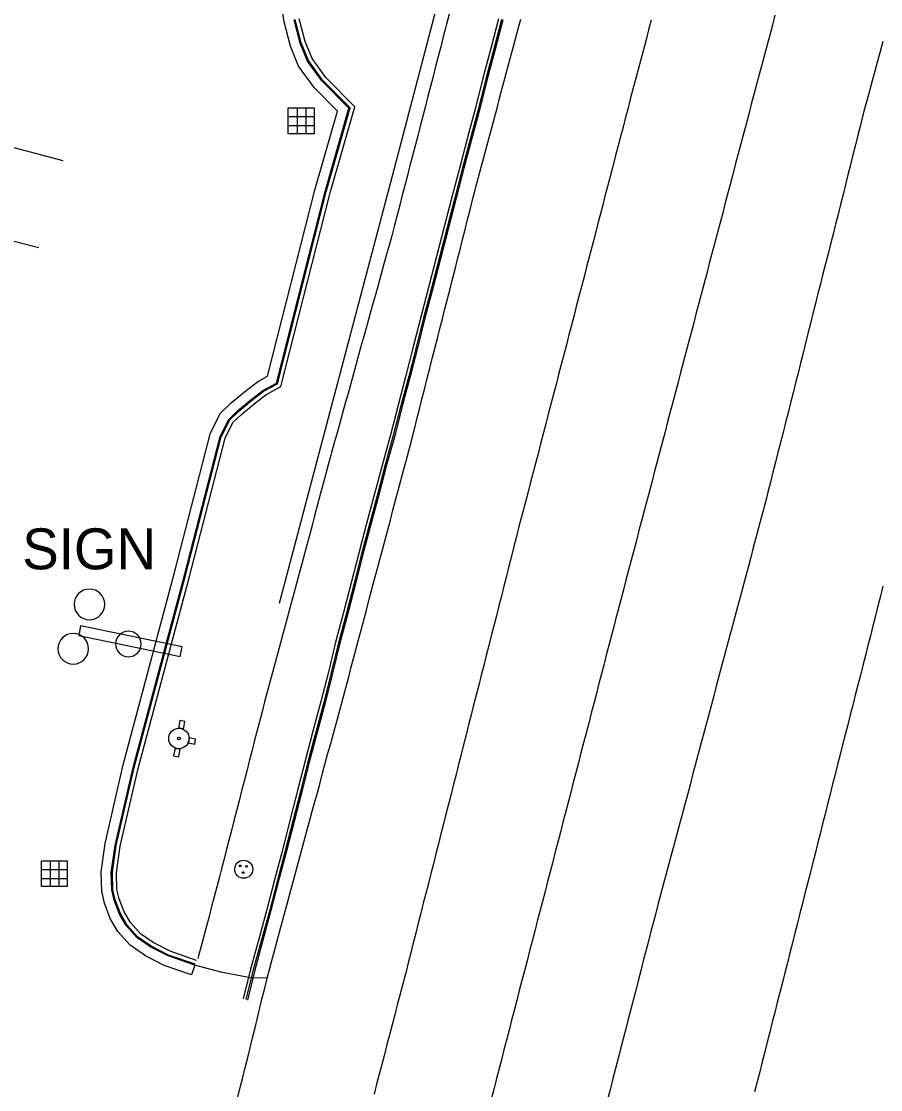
# Model space of a CAD drawing. Extents: x 1901471 to 1963503, y 756461 to 799997.
# Drawn here: x 1929483.1 to 1929567.1, y 772408.7 to 772513.2 of the extents above; entities that cross this region are included whole.
import ezdxf

# ---------------------------------------------------------------- set-up
doc = ezdxf.new("R2010")
doc.units = 0
for name, color, linetype in [('Default', 7, 'Continuous'), ('RD_EX_Bldg', 7, 'Continuous'), ('RD_EX_Conc', 7, 'Continuous'), ('RD_EX_DR_Inlet', 7, 'Continuous'), ('RD_EX_Fence_Other', 7, 'Continuous'), ('RD_EX_Misc', 7, 'Continuous'), ('RD_EX_Road', 7, 'Continuous'), ('RD_EX_UT', 7, 'Continuous'), ('RD_HC_Cl', 7, 'Continuous')]:
    doc.layers.add(name, color=color, linetype=linetype)

# ---------------------------------------------------------------- blocks, each defined once
blk = doc.blocks.new('POST')
at = {"layer": 'Default'}
for start, end in [(90, 270), (270, 90)]:
    blk.add_arc((0, 0), 0.127, start, end, dxfattribs=at)
blk = doc.blocks.new('MH')
at = {"layer": 'RD_EX_DR_Inlet'}
for centre, radius in [((0, 0), 1.75), ((-0.66, 0.63), 0.175), ((0.56, 0.56), 0.175), ((-0.09, -0.66), 0.175)]:
    blk.add_circle(centre, radius, dxfattribs=at)
blk = doc.blocks.new('SIGNPOST')
at = {"layer": 'Default'}
for start, end in [(90, 270), (270, 90)]:
    blk.add_arc((0, 0), 0.127, start, end, dxfattribs=at)
blk = doc.blocks.new('DI')
at = {"layer": 'RD_EX_DR_Inlet'}
for p, q in [((-0.84, 2.56), (-0.84, -2.44)), ((0.86, 2.56), (0.86, -2.44)), ((-2.54, 0.86), (2.46, 0.86)), ((-2.54, -0.84), (2.46, -0.84))]:
    blk.add_line(p, q, dxfattribs=at)
blk.add_lwpolyline([(-2.54, -2.44), (-2.54, 2.56), (2.46, 2.56), (2.46, -2.44)], close=True, dxfattribs=at)

msp = doc.modelspace()

# ---------------------------------------------------------------- linework, layer by layer
at = {"layer": 'RD_EX_Bldg'}
msp.add_lwpolyline([(1929488.71, 772453.14), (1929498.62, 772451.09), (1929498.81, 772452.03), (1929488.9, 772454.09)], close=True, dxfattribs=at)
at = {"layer": 'RD_EX_Conc'}
for points in [[(1929500.07, 772420.91), (1929497.46, 772421.81), (1929495.75, 772422.68), (1929494.4, 772423.6), (1929493.36, 772424.78), (1929492.71, 772425.91), (1929492.18, 772427.26), (1929491.95, 772428.26), (1929491.9, 772429.97), (1929492.28, 772432.62), (1929494.03, 772440.25), (1929499.05, 772459.04), (1929502.55, 772472.6), (1929503.38, 772474.27), (1929504.28, 772475.14), (1929505.54, 772476.19), (1929506.72, 772477.1), (1929508.05, 772477.81), (1929512.8, 772496.54), (1929515.13, 772504.7), (1929512.49, 772507.36), (1929511.09, 772509.3), (1929510.37, 772511.05), (1929509.78, 772513.34)], [(1929500.11, 772421), (1929497.5, 772421.9), (1929495.8, 772422.76), (1929494.47, 772423.68), (1929493.45, 772424.83), (1929492.8, 772425.95), (1929492.27, 772427.29), (1929492.05, 772428.27), (1929492, 772429.97), (1929492.37, 772432.6), (1929494.12, 772440.23), (1929499.15, 772459.02), (1929502.64, 772472.56), (1929503.47, 772474.21), (1929504.35, 772475.06), (1929505.6, 772476.11), (1929506.78, 772477.01), (1929508.13, 772477.74), (1929512.9, 772496.51), (1929515.25, 772504.73), (1929512.56, 772507.42), (1929511.17, 772509.35), (1929510.47, 772511.09), (1929509.88, 772513.36)], [(1929500.24, 772421.38), (1929497.65, 772422.27), (1929496, 772423.11), (1929494.74, 772423.98), (1929493.77, 772425.07), (1929493.16, 772426.12), (1929492.66, 772427.41), (1929492.45, 772428.32), (1929492.4, 772429.95), (1929492.77, 772432.53), (1929494.51, 772440.13), (1929499.54, 772458.92), (1929503.02, 772472.42), (1929503.79, 772473.97), (1929504.62, 772474.76), (1929505.85, 772475.8), (1929506.99, 772476.68), (1929508.48, 772477.47), (1929513.28, 772496.41), (1929515.7, 772504.84), (1929512.87, 772507.68), (1929511.53, 772509.54), (1929510.85, 772511.21), (1929510.27, 772513.44)], [(1929524.94, 772513.88), (1929524.68, 772512.92), (1929524.61, 772512.63), (1929524.35, 772511.66), (1929524.1, 772510.7), (1929523.85, 772509.73), (1929523.6, 772508.76), (1929523.35, 772507.79), (1929523.1, 772506.82), (1929522.85, 772505.86), (1929522.6, 772504.89), (1929522.35, 772503.92), (1929522.1, 772502.95), (1929521.85, 772501.98), (1929521.6, 772501.02), (1929521.34, 772500.05), (1929521.09, 772499.08), (1929520.84, 772498.11), (1929520.59, 772497.14), (1929520.34, 772496.18), (1929520.09, 772495.21), (1929519.84, 772494.24), (1929519.59, 772493.27), (1929519.32, 772492.22), (1929519.05, 772491.26), (1929518.78, 772490.29), (1929518.51, 772489.33), (1929518.25, 772488.37), (1929517.98, 772487.4), (1929517.71, 772486.44), (1929517.44, 772485.48), (1929517.18, 772484.51), (1929516.91, 772483.55), (1929516.64, 772482.59), (1929516.37, 772481.62), (1929516.11, 772480.66), (1929515.84, 772479.69), (1929515.57, 772478.73), (1929515.3, 772477.77), (1929515.04, 772476.8), (1929514.77, 772475.84), (1929514.5, 772474.88), (1929514.23, 772473.91), (1929513.97, 772472.95), (1929513.7, 772471.99), (1929513.43, 772471.02), (1929513.36, 772470.78), (1929513.36, 772470.78), (1929513.1, 772469.81), (1929512.84, 772468.85), (1929512.58, 772467.88), (1929512.32, 772466.92), (1929512.07, 772465.95), (1929511.81, 772464.98), (1929511.55, 772464.02), (1929511.29, 772463.05), (1929511.03, 772462.09), (1929510.77, 772461.12), (1929510.51, 772460.16), (1929510.25, 772459.19), (1929509.99, 772458.22), (1929509.73, 772457.26), (1929509.47, 772456.29), (1929509.21, 772455.33), (1929508.95, 772454.36), (1929508.69, 772453.4), (1929508.43, 772452.43), (1929508.17, 772451.46), (1929507.91, 772450.5), (1929507.65, 772449.53), (1929507.4, 772448.57), (1929507.14, 772447.6), (1929506.88, 772446.65), (1929506.63, 772445.68), (1929506.38, 772444.71), (1929506.13, 772443.75), (1929505.88, 772442.78), (1929505.64, 772441.81), (1929505.39, 772440.84), (1929505.14, 772439.87), (1929504.89, 772438.9), (1929504.64, 772437.94), (1929504.39, 772436.97), (1929504.14, 772436), (1929503.89, 772435.03), (1929503.64, 772434.06), (1929503.39, 772433.09), (1929503.14, 772432.12), (1929502.9, 772431.16), (1929502.65, 772430.19), (1929502.48, 772429.54), (1929502.22, 772428.57), (1929501.96, 772427.6), (1929501.7, 772426.64), (1929501.45, 772425.67), (1929501.19, 772424.71), (1929500.93, 772423.74), (1929500.67, 772422.77), (1929500.41, 772421.81), (1929500.35, 772421.56)], [(1929529.76, 772513.44), (1929529, 772510.53), (1929528.22, 772507.64), (1929527.5, 772504.73), (1929526.73, 772501.83), (1929525.96, 772498.93), (1929525.19, 772496), (1929524.45, 772493.09), (1929523.7, 772490.19), (1929522.94, 772487.29), (1929522.18, 772484.39), (1929521.44, 772481.48), (1929520.69, 772478.57), (1929519.93, 772475.67), (1929519.18, 772472.77), (1929518.4, 772469.9), (1929517.63, 772467), (1929516.86, 772464.1), (1929516.09, 772461.2), (1929515.36, 772458.29), (1929514.6, 772455.39), (1929513.83, 772452.49), (1929513.12, 772449.57), (1929512.38, 772446.68), (1929511.61, 772443.78), (1929510.84, 772440.88), (1929510.11, 772437.97), (1929509.36, 772435.06), (1929508.62, 772432.15), (1929507.85, 772429.25), (1929507.09, 772426.35), (1929506.33, 772423.45), (1929505.52, 772420.52), (1929504.8, 772417.61)], [(1929530.04, 772513.36), (1929529.28, 772510.46), (1929528.5, 772507.56), (1929527.78, 772504.65), (1929527.01, 772501.75), (1929526.24, 772498.85), (1929525.47, 772495.93), (1929524.73, 772493.02), (1929523.98, 772490.12), (1929523.22, 772487.22), (1929522.46, 772484.31), (1929521.72, 772481.41), (1929520.97, 772478.5), (1929520.21, 772475.6), (1929519.46, 772472.7), (1929518.67, 772469.82), (1929517.91, 772466.92), (1929517.14, 772464.02), (1929516.37, 772461.12), (1929515.64, 772458.21), (1929514.88, 772455.31), (1929514.11, 772452.41), (1929513.39, 772449.5), (1929512.66, 772446.6), (1929511.89, 772443.7), (1929511.12, 772440.8), (1929510.38, 772437.89), (1929509.64, 772434.99), (1929508.9, 772432.08), (1929508.15, 772429.17), (1929507.39, 772426.27), (1929506.59, 772423.38), (1929505.77, 772420.46), (1929505.04, 772417.55)], [(1929530.17, 772513.33), (1929529.42, 772510.42), (1929528.63, 772507.53), (1929527.91, 772504.62), (1929527.14, 772501.72), (1929526.37, 772498.82), (1929525.61, 772495.9), (1929524.87, 772492.99), (1929524.11, 772490.09), (1929523.36, 772487.18), (1929522.59, 772484.28), (1929521.85, 772481.37), (1929521.1, 772478.47), (1929520.34, 772475.57), (1929519.6, 772472.66), (1929518.81, 772469.79), (1929518.04, 772466.89), (1929517.27, 772463.99), (1929516.5, 772461.09), (1929515.77, 772458.18), (1929515.01, 772455.28), (1929514.24, 772452.38), (1929513.53, 772449.46), (1929512.79, 772446.56), (1929512.02, 772443.66), (1929511.25, 772440.76), (1929510.52, 772437.86), (1929509.77, 772434.95), (1929509.03, 772432.04), (1929508.24, 772429.15), (1929507.48, 772426.25), (1929506.72, 772423.35), (1929505.94, 772420.42), (1929505.22, 772417.5)]]:
    msp.add_lwpolyline(points, dxfattribs=at)
at = {"layer": 'RD_EX_Fence_Other'}
msp.add_lwpolyline([(1928943.66, 772569.06), (1928948.02, 772557.46), (1929021.66, 772575.26), (1929101.78, 772589.33), (1929188.62, 772597.69), (1929310.7, 772602.42), (1929440.73, 772595.88), (1929491.61, 772593.69), (1929530.87, 772541.97), (1929519.36, 772498.05), (1929508.31, 772456.27)], dxfattribs=at)
at = {"layer": 'RD_EX_Road'}
for points in [[(1929358.43, 772472.62), (1929362.51, 772488.71), (1929369.03, 772513.15), (1929371.76, 772520.59), (1929374.22, 772524.46), (1929376.33, 772526.91), (1929379.31, 772529.24), (1929382.39, 772531.08), (1929384.98, 772532.23), (1929388.07, 772533.27), (1929391.12, 772533.35), (1929395.88, 772533.08), (1929403.76, 772531.3), (1929421.33, 772526.61), (1929449.25, 772519.52), (1929472.26, 772513.28), (1929470.04, 772504.12), (1929487.16, 772499.59)], [(1929507.14, 772419.64), (1929505.5, 772419.67), (1929502.59, 772420.21), (1929500.07, 772420.91), (1929499.75, 772419.96), (1929497.07, 772420.88), (1929495.24, 772421.81), (1929493.73, 772422.85), (1929492.55, 772424.19), (1929491.8, 772425.47), (1929491.22, 772426.97), (1929490.96, 772428.14), (1929490.9, 772430.03), (1929491.29, 772432.8), (1929493.06, 772440.49), (1929498.09, 772459.3), (1929501.6, 772472.95), (1929502.57, 772474.87), (1929503.62, 772475.88), (1929504.91, 772476.97), (1929506.18, 772477.94), (1929507.18, 772478.48), (1929511.83, 772496.8), (1929514.01, 772504.41), (1929511.72, 772506.71), (1929510.2, 772508.81), (1929509.42, 772510.74), (1929508.8, 772513.14), (1929508.48, 772515.18)], [(1929504.27, 772407.99), (1929504.51, 772408.96), (1929504.75, 772409.93), (1929504.99, 772410.9), (1929505.23, 772411.87), (1929505.47, 772412.84), (1929505.71, 772413.82), (1929505.95, 772414.79), (1929506.19, 772415.76), (1929506.42, 772416.73), (1929506.66, 772417.7), (1929506.9, 772418.67), (1929507.14, 772419.64), (1929507.38, 772420.61), (1929507.58, 772421.35), (1929507.85, 772422.32), (1929508.11, 772423.28), (1929508.37, 772424.25), (1929508.63, 772425.21), (1929508.89, 772426.18), (1929509.16, 772427.14), (1929509.42, 772428.11), (1929509.68, 772429.07), (1929509.94, 772430.04), (1929510.2, 772431), (1929510.46, 772431.97), (1929510.73, 772432.93), (1929510.99, 772433.9), (1929511.25, 772434.86), (1929511.51, 772435.83), (1929511.77, 772436.79), (1929512.04, 772437.76), (1929512.3, 772438.72), (1929512.56, 772439.69), (1929512.82, 772440.65), (1929513.08, 772441.62), (1929513.35, 772442.58), (1929513.61, 772443.55), (1929513.87, 772444.51), (1929514.13, 772445.48), (1929514.39, 772446.44), (1929514.55, 772447.04), (1929514.81, 772448.01), (1929515.07, 772448.97), (1929515.32, 772449.94), (1929515.58, 772450.9), (1929515.84, 772451.87), (1929516.09, 772452.84), (1929516.35, 772453.8), (1929516.61, 772454.77), (1929516.87, 772455.74), (1929517.12, 772456.7), (1929517.38, 772457.67), (1929517.64, 772458.64), (1929517.89, 772459.6), (1929518.15, 772460.57), (1929518.41, 772461.53), (1929518.66, 772462.5), (1929518.92, 772463.47), (1929519.18, 772464.43), (1929519.43, 772465.4), (1929519.69, 772466.37), (1929519.95, 772467.33), (1929520.21, 772468.3), (1929520.46, 772469.27), (1929520.72, 772470.23), (1929520.98, 772471.2), (1929521.23, 772472.16), (1929521.31, 772472.48), (1929521.56, 772473.45), (1929521.81, 772474.42), (1929522.05, 772475.39), (1929522.3, 772476.36), (1929522.54, 772477.32), (1929522.79, 772478.29), (1929523.04, 772479.26), (1929523.28, 772480.23), (1929523.53, 772481.2), (1929523.78, 772482.17), (1929524.02, 772483.14), (1929524.27, 772484.11), (1929524.51, 772485.08), (1929524.76, 772486.05), (1929525.01, 772487.02), (1929525.25, 772487.99), (1929525.5, 772488.95), (1929525.74, 772489.92), (1929525.99, 772490.89), (1929526.24, 772491.86), (1929526.48, 772492.83), (1929526.73, 772493.8), (1929526.98, 772494.77), (1929527.22, 772495.74), (1929527.47, 772496.71), (1929527.54, 772496.98), (1929527.8, 772497.95), (1929528.06, 772498.91), (1929528.31, 772499.88), (1929528.57, 772500.84), (1929528.83, 772501.81), (1929529.09, 772502.78), (1929529.35, 772503.74), (1929529.61, 772504.71), (1929529.86, 772505.67), (1929530.12, 772506.64), (1929530.38, 772507.61), (1929530.64, 772508.57), (1929530.9, 772509.54), (1929531.16, 772510.5), (1929531.41, 772511.47), (1929531.67, 772512.44), (1929531.93, 772513.4)], [(1929544.68, 772513.31), (1929544.42, 772512.34), (1929544.17, 772511.38), (1929543.91, 772510.41), (1929543.66, 772509.44), (1929543.4, 772508.48), (1929543.14, 772507.51), (1929542.89, 772506.54), (1929542.63, 772505.58), (1929542.38, 772504.61), (1929542.17, 772503.82), (1929541.92, 772502.85), (1929541.67, 772501.88), (1929541.41, 772500.91), (1929541.16, 772499.95), (1929540.91, 772498.98), (1929540.66, 772498.01), (1929540.41, 772497.04), (1929540.15, 772496.08), (1929539.9, 772495.11), (1929539.65, 772494.14), (1929539.4, 772493.17), (1929539.15, 772492.2), (1929538.9, 772491.24), (1929538.64, 772490.27), (1929538.39, 772489.3), (1929538.14, 772488.33), (1929537.89, 772487.37), (1929537.64, 772486.4), (1929537.38, 772485.43), (1929537.13, 772484.46), (1929536.88, 772483.49), (1929536.63, 772482.53), (1929536.38, 772481.56), (1929536.13, 772480.59), (1929535.87, 772479.62), (1929535.62, 772478.66), (1929535.37, 772477.69), (1929535.12, 772476.72), (1929534.87, 772475.75), (1929534.61, 772474.78), (1929534.36, 772473.82), (1929534.11, 772472.85), (1929533.86, 772471.88), (1929533.61, 772470.91), (1929533.36, 772469.95), (1929533.1, 772468.98), (1929532.85, 772468.01), (1929532.6, 772467.04), (1929532.35, 772466.08), (1929532.1, 772465.11), (1929531.84, 772464.14), (1929531.75, 772463.78), (1929531.51, 772462.81), (1929531.26, 772461.85), (1929531.01, 772460.88), (1929530.77, 772459.91), (1929530.52, 772458.94), (1929530.27, 772457.97), (1929530.03, 772457), (1929529.78, 772456.03), (1929529.54, 772455.06), (1929529.29, 772454.09), (1929529.04, 772453.12), (1929528.8, 772452.15), (1929528.55, 772451.18), (1929528.31, 772450.22), (1929528.06, 772449.25), (1929527.81, 772448.28), (1929527.57, 772447.31), (1929527.32, 772446.34), (1929527.08, 772445.37), (1929526.83, 772444.4), (1929526.58, 772443.43), (1929526.34, 772442.46), (1929526.09, 772441.49), (1929525.85, 772440.52), (1929525.6, 772439.55), (1929525.35, 772438.59), (1929525.11, 772437.62), (1929524.86, 772436.65), (1929524.61, 772435.68), (1929524.37, 772434.71), (1929524.12, 772433.74), (1929523.88, 772432.77), (1929523.63, 772431.8), (1929523.38, 772430.83), (1929523.14, 772429.86), (1929522.89, 772428.89), (1929522.65, 772427.92), (1929522.4, 772426.96), (1929522.15, 772425.99), (1929521.91, 772425.02), (1929521.66, 772424.05), (1929521.42, 772423.08), (1929521.17, 772422.11), (1929520.92, 772421.14), (1929520.68, 772420.17), (1929520.61, 772419.92), (1929520.36, 772418.95), (1929520.11, 772417.98), (1929519.85, 772417.02), (1929519.6, 772416.05), (1929519.35, 772415.08), (1929519.1, 772414.11), (1929518.84, 772413.15), (1929518.59, 772412.18), (1929518.34, 772411.21), (1929518.08, 772410.25), (1929517.83, 772409.28), (1929517.58, 772408.31)], [(1929556.77, 772513.77), (1929556.52, 772512.8), (1929556.26, 772511.83), (1929556, 772510.87), (1929555.75, 772509.9), (1929555.49, 772508.93), (1929555.23, 772507.97), (1929554.98, 772507), (1929554.72, 772506.04), (1929554.46, 772505.07), (1929554.21, 772504.1), (1929553.95, 772503.14), (1929553.69, 772502.17), (1929553.43, 772501.2), (1929553.18, 772500.24), (1929553.15, 772500.14), (1929552.9, 772499.17), (1929552.64, 772498.21), (1929552.39, 772497.24), (1929552.13, 772496.27), (1929551.88, 772495.3), (1929551.63, 772494.34), (1929551.37, 772493.37), (1929551.12, 772492.4), (1929550.86, 772491.44), (1929550.61, 772490.47), (1929550.35, 772489.5), (1929550.1, 772488.53), (1929549.84, 772487.57), (1929549.59, 772486.6), (1929549.34, 772485.63), (1929549.08, 772484.67), (1929548.83, 772483.7), (1929548.57, 772482.73), (1929548.32, 772481.77), (1929548.06, 772480.8), (1929547.81, 772479.83), (1929547.55, 772478.86), (1929547.3, 772477.9), (1929547.05, 772476.93), (1929546.79, 772475.96), (1929546.54, 772475), (1929546.28, 772474.03), (1929546.03, 772473.06), (1929545.77, 772472.09), (1929545.52, 772471.13), (1929545.26, 772470.16), (1929545.01, 772469.19), (1929544.76, 772468.23), (1929544.5, 772467.26), (1929544.25, 772466.29), (1929543.99, 772465.33), (1929543.74, 772464.36), (1929543.48, 772463.39), (1929543.23, 772462.42), (1929542.98, 772461.46), (1929542.72, 772460.49), (1929542.47, 772459.52), (1929542.21, 772458.56), (1929541.96, 772457.59), (1929541.7, 772456.62), (1929541.45, 772455.65), (1929541.19, 772454.69), (1929541.08, 772454.24), (1929540.83, 772453.27), (1929540.57, 772452.3), (1929540.32, 772451.34), (1929540.07, 772450.37), (1929539.82, 772449.4), (1929539.57, 772448.43), (1929539.32, 772447.47), (1929539.07, 772446.5), (1929538.82, 772445.53), (1929538.57, 772444.56), (1929538.31, 772443.59), (1929538.06, 772442.63), (1929537.81, 772441.66), (1929537.56, 772440.69), (1929537.31, 772439.72), (1929537.06, 772438.76), (1929536.81, 772437.79), (1929536.56, 772436.82), (1929536.31, 772435.85), (1929536.05, 772434.88), (1929535.8, 772433.92), (1929535.55, 772432.95), (1929535.3, 772431.98), (1929535.05, 772431.01), (1929534.8, 772430.04), (1929534.55, 772429.08), (1929534.3, 772428.11), (1929534.05, 772427.14), (1929533.79, 772426.17), (1929533.54, 772425.21), (1929533.29, 772424.24), (1929533.04, 772423.27), (1929532.79, 772422.3), (1929532.54, 772421.33), (1929532.29, 772420.37), (1929532.04, 772419.4), (1929531.78, 772418.43), (1929531.53, 772417.46), (1929531.28, 772416.49), (1929531.03, 772415.53), (1929530.78, 772414.55), (1929530.53, 772413.58), (1929530.28, 772412.62), (1929530.03, 772411.65), (1929529.78, 772410.68), (1929529.53, 772409.71), (1929529.28, 772408.74), (1929529.03, 772407.78)], [(1929567.33, 772511.21), (1929567.07, 772510.24), (1929566.8, 772509.28), (1929566.54, 772508.32), (1929566.27, 772507.35), (1929566.01, 772506.39), (1929565.75, 772505.42), (1929565.63, 772504.98), (1929565.38, 772504.01), (1929565.14, 772503.04), (1929564.89, 772502.07), (1929564.65, 772501.1), (1929564.4, 772500.13), (1929564.16, 772499.16), (1929563.91, 772498.19), (1929563.67, 772497.22), (1929563.43, 772496.25), (1929563.18, 772495.28), (1929562.94, 772494.31), (1929562.69, 772493.34), (1929562.45, 772492.37), (1929562.2, 772491.4), (1929561.96, 772490.44), (1929561.72, 772489.47), (1929561.47, 772488.5), (1929561.23, 772487.53), (1929560.98, 772486.56), (1929560.74, 772485.59), (1929560.49, 772484.62), (1929560.25, 772483.65), (1929560, 772482.68), (1929559.76, 772481.71), (1929559.52, 772480.74), (1929559.27, 772479.77), (1929559.03, 772478.8), (1929558.78, 772477.83), (1929558.54, 772476.86), (1929558.29, 772475.89), (1929558.05, 772474.92), (1929557.81, 772473.95), (1929557.56, 772472.98), (1929557.32, 772472.01), (1929557.07, 772471.04), (1929556.83, 772470.07), (1929556.58, 772469.1), (1929556.34, 772468.13), (1929556.09, 772467.16), (1929555.94, 772466.56), (1929555.68, 772465.59), (1929555.43, 772464.63), (1929555.17, 772463.66), (1929554.91, 772462.69), (1929554.65, 772461.73), (1929554.4, 772460.76), (1929554.14, 772459.8), (1929553.88, 772458.83), (1929553.62, 772457.86), (1929553.36, 772456.9), (1929553.11, 772455.93), (1929552.85, 772454.97), (1929552.59, 772454), (1929552.33, 772453.03), (1929552.08, 772452.07), (1929551.82, 772451.1), (1929551.56, 772450.13), (1929551.3, 772449.17), (1929551.04, 772448.2), (1929550.79, 772447.24), (1929550.53, 772446.27), (1929550.27, 772445.3), (1929550.01, 772444.34), (1929549.76, 772443.37), (1929549.5, 772442.41), (1929549.24, 772441.44), (1929548.98, 772440.47), (1929548.72, 772439.51), (1929548.47, 772438.54), (1929548.21, 772437.57), (1929547.95, 772436.61), (1929547.69, 772435.64), (1929547.44, 772434.68), (1929547.18, 772433.71), (1929546.92, 772432.74), (1929546.66, 772431.78), (1929546.4, 772430.81), (1929546.15, 772429.85), (1929545.89, 772428.88), (1929545.63, 772427.91), (1929545.37, 772426.95), (1929545.12, 772425.98), (1929544.86, 772425.01), (1929544.68, 772424.36), (1929544.43, 772423.39), (1929544.18, 772422.42), (1929543.93, 772421.45), (1929543.68, 772420.48), (1929543.44, 772419.52), (1929543.19, 772418.55), (1929542.94, 772417.58), (1929542.69, 772416.61), (1929542.44, 772415.64), (1929542.19, 772414.67), (1929541.94, 772413.71), (1929541.69, 772412.74), (1929541.44, 772411.77), (1929541.19, 772410.8), (1929540.94, 772409.83), (1929540.69, 772408.86), (1929540.44, 772407.9)], [(1929467.87, 772495.36), (1929484.82, 772491.06)], [(1929567.33, 772457.97), (1929567.08, 772457), (1929566.84, 772456.03), (1929566.59, 772455.06), (1929566.34, 772454.09), (1929566.1, 772453.12), (1929565.85, 772452.16), (1929565.61, 772451.19), (1929565.36, 772450.22), (1929565.12, 772449.25), (1929564.87, 772448.28), (1929564.62, 772447.31), (1929564.38, 772446.34), (1929564.13, 772445.37), (1929563.89, 772444.4), (1929563.64, 772443.43), (1929563.39, 772442.46), (1929563.15, 772441.49), (1929562.9, 772440.52), (1929562.66, 772439.56), (1929562.41, 772438.59), (1929562.17, 772437.62), (1929561.92, 772436.65), (1929561.67, 772435.68), (1929561.43, 772434.71), (1929561.18, 772433.74), (1929560.94, 772432.77), (1929560.69, 772431.8), (1929560.44, 772430.83), (1929560.2, 772429.86), (1929559.95, 772428.89), (1929559.71, 772427.92), (1929559.46, 772426.95), (1929559.22, 772425.99), (1929558.97, 772425.02), (1929558.72, 772424.05), (1929558.48, 772423.08), (1929558.23, 772422.11), (1929557.99, 772421.14), (1929557.74, 772420.17), (1929557.5, 772419.2), (1929557.25, 772418.23), (1929557, 772417.26), (1929556.76, 772416.29), (1929556.51, 772415.32), (1929556.27, 772414.35), (1929556.02, 772413.39), (1929555.77, 772412.42), (1929555.53, 772411.45), (1929555.28, 772410.48), (1929555.04, 772409.51), (1929554.79, 772408.54)]]:
    msp.add_lwpolyline(points, dxfattribs=at)
at = {"layer": 'RD_EX_UT'}
for p, q in [((1929498.6, 772444.82), (1929498.47, 772444.07)), ((1929499.09, 772444.73), (1929498.6, 772444.82)), ((1929498.96, 772443.96), (1929499.09, 772444.73)), ((1929500.14, 772443.02), (1929499.51, 772443.13)), ((1929500.05, 772442.52), (1929500.14, 772443.02)), ((1929498.13, 772442.14), (1929497.99, 772441.37)), ((1929498.49, 772441.28), (1929498.63, 772442.08)), ((1929499.41, 772442.64), (1929500.05, 772442.52)), ((1929497.99, 772441.37), (1929498.49, 772441.28))]:
    msp.add_line(p, q, dxfattribs=at)
for radius in [1, 0.125]:
    msp.add_circle((1929498.51, 772443.07), radius, dxfattribs=at)
for start, end in [(63.3387, 92.315), (334.2455, 3.2128), (247.685, 276.6613)]:
    msp.add_arc((1929498.51, 772443.07), 1, start, end, dxfattribs=at)
at = {"layer": 'RD_HC_Cl'}
for centre, radius, start, end in [((1933934.02, 762479.74), 11482.38, 112.01316, 122.84589), ((1933920.67, 762509.14), 11420.5, 112.014247, 122.846378), ((1933910.03, 762523.4), 11373.86, 112.013249, 123.541888)]:
    msp.add_arc(centre, radius, start, end, dxfattribs=at)

# ---------------------------------------------------------------- block references
at = {"layer": 'RD_EX_Bldg', "xscale": 9.84251968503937, "yscale": 9.84251968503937}
msp.add_blockref('SIGNPOST', (1929493.57, 772452.31), dxfattribs=at)
at = {"layer": 'RD_EX_DR_Inlet', "xscale": 0.5039370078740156, "yscale": 0.5039370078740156}
for name, p in [('DI', (1929510.48, 772503.43)), ('DI', (1929486.34, 772429.82)), ('MH', (1929504.84, 772430.29))]:
    msp.add_blockref(name, p, dxfattribs=at)
at = {"layer": 'RD_EX_Misc', "xscale": 11.811023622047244, "yscale": 11.811023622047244}
for p in [(1929489.76, 772456.18), (1929488.18, 772451.84)]:
    msp.add_blockref('POST', p, dxfattribs=at)

# ---------------------------------------------------------------- texts
at = {"layer": 'RD_EX_Road'}
msp.add_text('SIGN', height=4, dxfattribs=at).set_placement((1929483.19, 772459.61))

doc.saveas('drawing.dxf')
